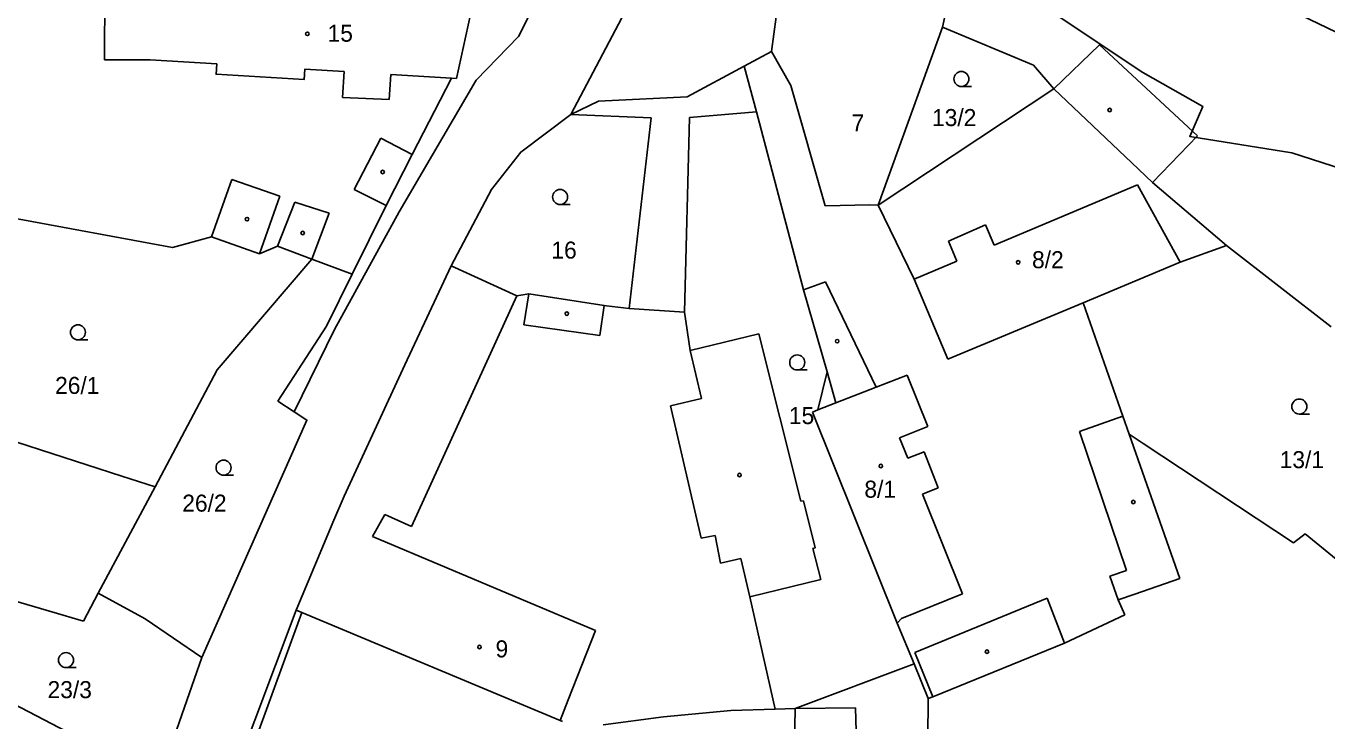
# Model space of a CAD drawing. Extents: x -743888 to -742027, y -1128394 to -1126768.
# Drawn here: x -742956.8 to -742827, y -1127501.6 to -1127432.2 of the extents above; entities that cross this region are included whole.
import ezdxf

# ---------------------------------------------------------------- set-up
doc = ezdxf.new("R2010")
doc.units = 0
for name, color, linetype in [('Vrstva 1', 7, 'Continuous'), ('Vrstva 18', 7, 'Continuous'), ('Vrstva 19', 7, 'Continuous'), ('Vrstva 25', 7, 'Continuous'), ('Vrstva 3', 7, 'Continuous'), ('Vrstva 37', 7, 'Continuous'), ('Vrstva 4', 7, 'Continuous'), ('Vrstva 52', 7, 'Continuous'), ('Vrstva 6', 7, 'Continuous')]:
    doc.layers.add(name, color=color, linetype=linetype)

msp = doc.modelspace()

# ---------------------------------------------------------------- linework, layer by layer
at = {"layer": 'Vrstva 1'}
for points in [[(-742907.65, -1127433.29), (-742900.6, -1127419.3)], [(-742902.44, -1127441.06), (-742891.64, -1127420.53)], [(-742839.78, -1127426.23), (-742821.85, -1127434.87)], [(-742865.34, -1127432.36), (-742864.82, -1127429.91)], [(-742913.85, -1127437.46), (-742912.45, -1127431.08)], [(-742911.88, -1127437.64), (-742907.65, -1127433.29)], [(-742871.77, -1127450.12), (-742865.34, -1127432.36)], [(-742865.34, -1127432.36), (-742856.26, -1127436.13)], [(-742856.26, -1127436.13), (-742854.25, -1127438.49)], [(-742918.26, -1127445.05), (-742914.35, -1127437.43)], [(-742914.35, -1127437.43), (-742913.85, -1127437.46)], [(-742919.56, -1127450.77), (-742911.88, -1127437.64)], [(-742871.77, -1127450.12), (-742854.25, -1127438.49)], [(-742854.25, -1127438.49), (-742846.46, -1127445.88)], [(-742907.43, -1127444.81), (-742902.44, -1127441.06)], [(-742902.44, -1127441.06), (-742894.41, -1127441.4)], [(-742890.59, -1127441.38), (-742883.9, -1127440.8)], [(-742883.9, -1127440.8), (-742879.22, -1127458.57)], [(-742896.63, -1127460.43), (-742894.41, -1127441.4)], [(-742891.11, -1127460.79), (-742890.59, -1127441.38)], [(-742920.88, -1127450.15), (-742918.26, -1127445.05)], [(-742910.36, -1127448.54), (-742907.43, -1127444.81)], [(-742846.46, -1127445.88), (-742844.39, -1127447.86)], [(-742844.39, -1127447.86), (-742837, -1127454.13)], [(-742914.39, -1127456.16), (-742910.36, -1127448.54)], [(-742924.26, -1127457.02), (-742920.88, -1127450.15)], [(-742872.62, -1127450.07), (-742871.77, -1127450.12)], [(-742871.77, -1127450.12), (-742868.19, -1127457.49)], [(-742958.39, -1127451.34), (-742942.2, -1127454.33)], [(-742926.01, -1127462.54), (-742919.56, -1127450.77)], [(-742942.2, -1127454.33), (-742938.29, -1127453.29)], [(-742938.29, -1127453.29), (-742933.5, -1127454.97)], [(-742933.5, -1127454.97), (-742931.72, -1127454.21)], [(-742931.72, -1127454.21), (-742928.29, -1127455.5)], [(-742841.64, -1127455.8), (-742837, -1127454.13)], [(-742837, -1127454.13), (-742826.58, -1127462.26)], [(-742918.99, -1127466.07), (-742914.39, -1127456.16)], [(-742914.39, -1127456.16), (-742907.82, -1127459.15)], [(-742851.33, -1127459.86), (-742841.64, -1127455.8)], [(-742926.81, -1127462.21), (-742924.26, -1127457.02)], [(-742868.19, -1127457.49), (-742864.81, -1127465.5)], [(-742907.82, -1127459.15), (-742906.63, -1127458.97)], [(-742906.63, -1127458.97), (-742899.1, -1127460.13)], [(-742879.22, -1127458.57), (-742876.85, -1127466.76)], [(-742899.1, -1127460.13), (-742898.88, -1127460.16)], [(-742898.88, -1127460.16), (-742896.63, -1127460.43)], [(-742891.11, -1127460.79), (-742890.54, -1127464.62)], [(-742864.81, -1127465.5), (-742851.33, -1127459.86)], [(-742851.33, -1127459.86), (-742847.35, -1127471.19)], [(-742930.03, -1127470.75), (-742926.01, -1127462.54)], [(-742890.54, -1127464.62), (-742883.68, -1127462.97)], [(-742883.68, -1127462.97), (-742879.48, -1127479.68)], [(-742925.07, -1127479.17), (-742918.99, -1127466.07)], [(-742877.79, -1127470.55), (-742876.01, -1127469.85)], [(-742968.23, -1127470.39), (-742947.25, -1127477.16)], [(-742930.03, -1127470.75), (-742928.77, -1127471.57)], [(-742878.34, -1127470.77), (-742877.79, -1127470.55)], [(-742878.34, -1127470.77), (-742869.89, -1127491.86)], [(-742847.35, -1127471.19), (-742846.72, -1127472.99)], [(-742939.27, -1127495.28), (-742928.77, -1127471.57)], [(-742846.72, -1127472.99), (-742845.32, -1127473.92)], [(-742846.72, -1127472.99), (-742841.67, -1127487.38)], [(-742845.32, -1127473.92), (-742830.34, -1127483.83)], [(-742926.08, -1127481.57), (-742925.07, -1127479.17)], [(-742879.48, -1127479.68), (-742879.23, -1127479.62)], [(-742879.23, -1127479.62), (-742878.05, -1127484.32)], [(-742929.86, -1127490.53), (-742926.08, -1127481.57)], [(-742830.34, -1127483.83), (-742829.18, -1127482.91)], [(-742829.18, -1127482.91), (-742822.98, -1127487.99)], [(-742977.71, -1127483.81), (-742954.21, -1127490.71)], [(-742878.29, -1127484.38), (-742878.05, -1127484.32)], [(-742878.29, -1127484.38), (-742877.51, -1127487.49)], [(-742884.58, -1127489.2), (-742877.51, -1127487.49)], [(-742846.17, -1127488.94), (-742841.67, -1127487.38)], [(-742949.6, -1127488.85), (-742944.9, -1127491.4)], [(-742884.58, -1127489.2), (-742882.05, -1127500.43)], [(-742847.83, -1127489.51), (-742846.17, -1127488.94)], [(-742944.28, -1127528.98), (-742929.86, -1127490.53)], [(-742929.86, -1127490.53), (-742929.27, -1127490.78)], [(-742847.83, -1127489.51), (-742847.16, -1127491.01)], [(-742974.21, -1127491.49), (-742943.52, -1127507.49)], [(-742944.9, -1127491.4), (-742939.27, -1127495.28)], [(-742929.27, -1127490.78), (-742903.5, -1127501.56)], [(-742869.89, -1127491.86), (-742868.18, -1127495.92)], [(-742853.18, -1127493.83), (-742847.16, -1127491.01)], [(-742866.31, -1127499.19), (-742853.18, -1127493.83)], [(-742943.52, -1127507.49), (-742939.27, -1127495.28)], [(-742880.06, -1127500.37), (-742868.18, -1127495.92)], [(-742868.18, -1127495.92), (-742866.77, -1127499.38)], [(-742866.85, -1127507.25), (-742866.77, -1127499.38)], [(-742866.77, -1127499.38), (-742866.31, -1127499.19)], [(-742893.18, -1127501.21), (-742886.47, -1127500.55)], [(-742886.47, -1127500.55), (-742882.05, -1127500.43)], [(-742882.05, -1127500.43), (-742880.06, -1127500.37)], [(-742880.06, -1127500.37), (-742874.03, -1127500.28)], [(-742874.03, -1127500.28), (-742873.82, -1127507.33)], [(-742903.5, -1127501.56), (-742903.28, -1127501.66)], [(-742899.22, -1127501.99), (-742893.18, -1127501.21)]]:
    msp.add_lwpolyline(points, dxfattribs=at)
at = {"layer": 'Vrstva 25'}
for p, q in [((-742863.47, -1127438.27), (-742862.47, -1127438.27)), ((-742903.51, -1127450.05), (-742902.51, -1127450.05)), ((-742951.62, -1127463.56), (-742950.62, -1127463.56)), ((-742879.85, -1127466.57), (-742878.85, -1127466.57)), ((-742829.75, -1127470.97), (-742828.75, -1127470.97)), ((-742937.09, -1127477.07), (-742936.09, -1127477.07)), ((-742952.81, -1127496.28), (-742951.81, -1127496.28))]:
    msp.add_line(p, q, dxfattribs=at)
for centre, radius in [((-742928.73, -1127433.01), 0.175), ((-742863.47, -1127437.52), 0.75), ((-742848.67, -1127440.62), 0.175), ((-742921.22, -1127446.8), 0.175), ((-742903.51, -1127449.3), 0.75), ((-742934.75, -1127451.51), 0.175), ((-742929.19, -1127452.9), 0.175), ((-742857.81, -1127455.82), 0.175), ((-742902.84, -1127460.94), 0.175), ((-742951.62, -1127462.81), 0.75), ((-742875.86, -1127463.69), 0.175), ((-742879.85, -1127465.82), 0.75), ((-742829.75, -1127470.22), 0.75), ((-742937.09, -1127476.32), 0.75), ((-742871.51, -1127476.16), 0.175), ((-742885.61, -1127477.06), 0.175), ((-742846.32, -1127479.75), 0.175), ((-742911.55, -1127494.23), 0.175), ((-742860.92, -1127494.69), 0.175), ((-742952.81, -1127495.53), 0.75)]:
    msp.add_circle(centre, radius, dxfattribs=at)
at = {"layer": 'Vrstva 3'}
for points in [[(-742948.97, -1127435.6), (-742948.92, -1127428.77)], [(-742913.85, -1127437.46), (-742912.45, -1127431.08)], [(-742948.97, -1127435.6), (-742944.4, -1127435.62)], [(-742944.4, -1127435.62), (-742937.77, -1127436.02), (-742937.83, -1127437.05), (-742929.04, -1127437.56), (-742928.98, -1127436.55), (-742925.07, -1127436.78)], [(-742925.23, -1127439.38), (-742925.07, -1127436.78)], [(-742920.55, -1127439.56), (-742920.4, -1127437.06)], [(-742920.4, -1127437.06), (-742914.35, -1127437.43)], [(-742914.35, -1127437.43), (-742913.85, -1127437.46)], [(-742925.23, -1127439.38), (-742920.55, -1127439.56)], [(-742860.19, -1127454.12), (-742845.89, -1127448.09)], [(-742845.89, -1127448.09), (-742841.64, -1127455.8)], [(-742864.75, -1127453.71), (-742861.05, -1127452.08)], [(-742861.05, -1127452.08), (-742860.19, -1127454.12)], [(-742864.75, -1127453.71), (-742863.91, -1127455.69)], [(-742918.99, -1127466.07), (-742914.39, -1127456.16)], [(-742914.39, -1127456.16), (-742907.82, -1127459.15)], [(-742868.19, -1127457.49), (-742863.91, -1127455.69)], [(-742851.33, -1127459.86), (-742841.64, -1127455.8)], [(-742868.19, -1127457.49), (-742864.81, -1127465.5)], [(-742918.33, -1127482.18), (-742907.82, -1127459.15)], [(-742864.81, -1127465.5), (-742851.33, -1127459.86)], [(-742925.07, -1127479.17), (-742918.99, -1127466.07)], [(-742871.96, -1127468.27), (-742868.89, -1127467.07)], [(-742868.89, -1127467.07), (-742866.83, -1127472.22)], [(-742876.01, -1127469.85), (-742871.96, -1127468.27)], [(-742877.79, -1127470.55), (-742876.01, -1127469.85)], [(-742878.34, -1127470.77), (-742877.79, -1127470.55)], [(-742878.34, -1127470.77), (-742869.89, -1127491.86)], [(-742869.63, -1127473.35), (-742866.83, -1127472.22)], [(-742869.63, -1127473.35), (-742868.81, -1127475.38)], [(-742868.81, -1127475.38), (-742867.18, -1127474.73)], [(-742867.18, -1127474.73), (-742865.78, -1127478.33)], [(-742867.36, -1127478.97), (-742865.78, -1127478.33)], [(-742867.36, -1127478.97), (-742863.35, -1127488.93)], [(-742926.08, -1127481.57), (-742925.07, -1127479.17)], [(-742929.86, -1127490.53), (-742926.08, -1127481.57)], [(-742922.23, -1127483.19), (-742921.01, -1127480.98)], [(-742921.01, -1127480.98), (-742918.33, -1127482.18)], [(-742922.23, -1127483.19), (-742899.99, -1127492.58)], [(-742869.46, -1127491.38), (-742863.35, -1127488.93)], [(-742929.86, -1127490.53), (-742929.27, -1127490.78)], [(-742929.27, -1127490.78), (-742903.5, -1127501.56)], [(-742869.89, -1127491.86), (-742869.46, -1127491.38)], [(-742902.7, -1127499.5), (-742899.99, -1127492.58)], [(-742903.5, -1127501.56), (-742902.7, -1127499.5)], [(-742893.18, -1127501.21), (-742886.47, -1127500.55)], [(-742886.47, -1127500.55), (-742882.05, -1127500.43)], [(-742882.05, -1127500.43), (-742880.06, -1127500.37)], [(-742880.13, -1127503.99), (-742880.06, -1127500.37)], [(-742899.22, -1127501.99), (-742893.18, -1127501.21)]]:
    msp.add_lwpolyline(points, dxfattribs=at)
at = {"layer": 'Vrstva 37'}
for centre in [(-742928.73, -1127433.01), (-742857.81, -1127455.82), (-742871.51, -1127476.16), (-742911.55, -1127494.23)]:
    msp.add_circle(centre, 0.175, dxfattribs=at)
at = {"layer": 'Vrstva 4'}
for points in [[(-742948.97, -1127435.6), (-742948.92, -1127428.77)], [(-742854.25, -1127438.49), (-742849.69, -1127434.12)], [(-742849.69, -1127434.12), (-742839.92, -1127443.21)], [(-742948.97, -1127435.6), (-742944.4, -1127435.62)], [(-742944.4, -1127435.62), (-742937.77, -1127436.02), (-742937.83, -1127437.05), (-742929.04, -1127437.56), (-742928.98, -1127436.55), (-742925.07, -1127436.78)], [(-742925.23, -1127439.38), (-742925.07, -1127436.78)], [(-742920.55, -1127439.56), (-742920.4, -1127437.06)], [(-742920.4, -1127437.06), (-742914.35, -1127437.43)], [(-742925.23, -1127439.38), (-742920.55, -1127439.56)], [(-742924.06, -1127448.56), (-742921.41, -1127443.43)], [(-742921.41, -1127443.43), (-742918.26, -1127445.05)], [(-742844.39, -1127447.86), (-742839.92, -1127443.21)], [(-742938.29, -1127453.29), (-742936.28, -1127447.55)], [(-742936.28, -1127447.55), (-742931.49, -1127449.23)], [(-742924.06, -1127448.56), (-742920.88, -1127450.15)], [(-742860.19, -1127454.12), (-742845.89, -1127448.09)], [(-742845.89, -1127448.09), (-742841.64, -1127455.8)], [(-742933.5, -1127454.97), (-742931.49, -1127449.23)], [(-742931.72, -1127454.21), (-742929.99, -1127449.82)], [(-742929.99, -1127449.82), (-742926.56, -1127450.92)], [(-742928.29, -1127455.5), (-742926.56, -1127450.92)], [(-742864.75, -1127453.71), (-742861.05, -1127452.08)], [(-742861.05, -1127452.08), (-742860.19, -1127454.12)], [(-742864.75, -1127453.71), (-742863.91, -1127455.69)], [(-742868.19, -1127457.49), (-742863.91, -1127455.69)], [(-742879.22, -1127458.57), (-742877.04, -1127457.77)], [(-742877.04, -1127457.77), (-742871.96, -1127468.27)], [(-742918.33, -1127482.18), (-742907.82, -1127459.15)], [(-742907.14, -1127462.06), (-742906.63, -1127458.97)], [(-742899.53, -1127463.11), (-742899.1, -1127460.13)], [(-742896.63, -1127460.43), (-742891.11, -1127460.79)], [(-742907.14, -1127462.06), (-742899.53, -1127463.11)], [(-742890.54, -1127464.62), (-742889.4, -1127469.4)], [(-742877.79, -1127470.55), (-742876.85, -1127466.76)], [(-742871.96, -1127468.27), (-742868.89, -1127467.07)], [(-742868.89, -1127467.07), (-742866.83, -1127472.22)], [(-742876.01, -1127469.85), (-742871.96, -1127468.27)], [(-742892.5, -1127470.14), (-742889.4, -1127469.4)], [(-742892.5, -1127470.14), (-742889.45, -1127483.37)], [(-742851.7, -1127472.72), (-742847.35, -1127471.19)], [(-742869.63, -1127473.35), (-742866.83, -1127472.22)], [(-742869.63, -1127473.35), (-742868.81, -1127475.38)], [(-742851.7, -1127472.72), (-742846.98, -1127486.57)], [(-742868.81, -1127475.38), (-742867.18, -1127474.73)], [(-742867.18, -1127474.73), (-742865.78, -1127478.33)], [(-742867.36, -1127478.97), (-742865.78, -1127478.33)], [(-742867.36, -1127478.97), (-742863.35, -1127488.93)], [(-742922.23, -1127483.19), (-742921.01, -1127480.98)], [(-742921.01, -1127480.98), (-742918.33, -1127482.18)], [(-742922.23, -1127483.19), (-742899.99, -1127492.58)], [(-742889.45, -1127483.37), (-742888.05, -1127483.09)], [(-742888.05, -1127483.09), (-742887.5, -1127485.85)], [(-742887.5, -1127485.85), (-742885.46, -1127485.38)], [(-742885.46, -1127485.38), (-742884.58, -1127489.2)], [(-742848.65, -1127487.14), (-742846.98, -1127486.57)], [(-742848.65, -1127487.14), (-742847.83, -1127489.51)], [(-742869.46, -1127491.38), (-742863.35, -1127488.93)], [(-742868.11, -1127494.78), (-742854.9, -1127489.36)], [(-742854.9, -1127489.36), (-742853.18, -1127493.83)], [(-742943.36, -1127529.4), (-742929.27, -1127490.78)], [(-742869.89, -1127491.86), (-742869.46, -1127491.38)], [(-742902.7, -1127499.5), (-742899.99, -1127492.58)], [(-742868.11, -1127494.78), (-742866.31, -1127499.19)], [(-742903.5, -1127501.56), (-742902.7, -1127499.5)], [(-742880.13, -1127503.99), (-742880.06, -1127500.37)]]:
    msp.add_lwpolyline(points, dxfattribs=at)
at = {"layer": 'Vrstva 52'}
for points in [[(-742972.89, -1127572.54), (-742971.19, -1127569.17), (-742967.51, -1127562.65), (-742960.97, -1127550.69), (-742958.07, -1127544.59), (-742952.01, -1127529.96), (-742951.87, -1127529.63), (-742949.93, -1127524.86), (-742947.48, -1127518.45), (-742943.52, -1127507.49), (-742939.27, -1127495.28), (-742928.77, -1127471.57), (-742930.03, -1127470.75), (-742926.01, -1127462.54), (-742919.56, -1127450.77), (-742911.88, -1127437.64), (-742907.65, -1127433.29), (-742900.6, -1127419.3), (-742892.14, -1127404.73), (-742890.15, -1127399.92)], [(-742965.26, -1127573.48), (-742964.75, -1127572.6), (-742958.43, -1127564.08), (-742954.72, -1127554.49), (-742950.97, -1127547.61), (-742944.28, -1127528.98), (-742929.86, -1127490.53), (-742926.08, -1127481.57), (-742925.07, -1127479.17), (-742918.99, -1127466.07), (-742914.39, -1127456.16), (-742910.36, -1127448.54), (-742907.43, -1127444.81), (-742902.44, -1127441.06), (-742891.64, -1127420.53), (-742883.68, -1127406.25)], [(-742883.68, -1127406.25), (-742877.77, -1127411.74), (-742873.23, -1127415.96), (-742864.44, -1127424.13), (-742863.69, -1127424.62), (-742845.38, -1127436.88), (-742839.38, -1127440.25), (-742840.69, -1127443.25), (-742830.5, -1127444.88), (-742808, -1127452.13), (-742784.69, -1127456.75), (-742774.5, -1127458.88), (-742749.06, -1127465.25), (-742728.25, -1127469.5)]]:
    msp.add_lwpolyline(points, dxfattribs=at)
at = {"layer": 'Vrstva 6'}
for points in [[(-742882.42, -1127434.76), (-742881.96, -1127431.32)], [(-742885.14, -1127436.23), (-742882.42, -1127434.76)], [(-742882.42, -1127434.76), (-742880.5, -1127438.16)], [(-742890.82, -1127439.3), (-742885.14, -1127436.23)], [(-742885.14, -1127436.23), (-742883.9, -1127440.8)], [(-742880.5, -1127438.16), (-742877.06, -1127450.18)], [(-742902.44, -1127441.06), (-742899.67, -1127439.74)], [(-742899.67, -1127439.74), (-742890.82, -1127439.3)], [(-742877.06, -1127450.18), (-742872.62, -1127450.07)], [(-742937.72, -1127466.57), (-742928.29, -1127455.5)], [(-742928.29, -1127455.5), (-742924.26, -1127457.02)], [(-742931.67, -1127469.68), (-742926.81, -1127462.21)], [(-742943.93, -1127478.23), (-742937.72, -1127466.57)], [(-742876.85, -1127466.76), (-742876.01, -1127469.85)], [(-742931.67, -1127469.68), (-742930.03, -1127470.75)], [(-742947.25, -1127477.16), (-742943.93, -1127478.23)], [(-742949.6, -1127488.85), (-742943.93, -1127478.23)], [(-742951.07, -1127491.63), (-742949.6, -1127488.85)], [(-742954.21, -1127490.71), (-742951.07, -1127491.63)]]:
    msp.add_lwpolyline(points, dxfattribs=at)

# ---------------------------------------------------------------- texts
at = {"layer": 'Vrstva 18'}
for s, p in [('13/2', (-742866.4, -1127442.22)), ('16', (-742904.38, -1127455.45)), ('26/1', (-742953.9, -1127468.96)), ('15', (-742880.68, -1127471.97)), ('13/1', (-742831.71, -1127476.37)), ('26/2', (-742941.21, -1127480.71)), ('23/3', (-742954.65, -1127499.33))]:
    msp.add_text(s, height=1.7, dxfattribs=at).set_placement(p)
at = {"layer": 'Vrstva 19'}
for s, p in [('15', (-742926.71, -1127433.8)), ('7', (-742874.42, -1127442.76)), ('8/2', (-742856.42, -1127456.41)), ('8/1', (-742873.15, -1127479.32)), ('9', (-742909.95, -1127495.26))]:
    msp.add_text(s, height=1.7, dxfattribs=at).set_placement(p)

doc.saveas('drawing.dxf')
